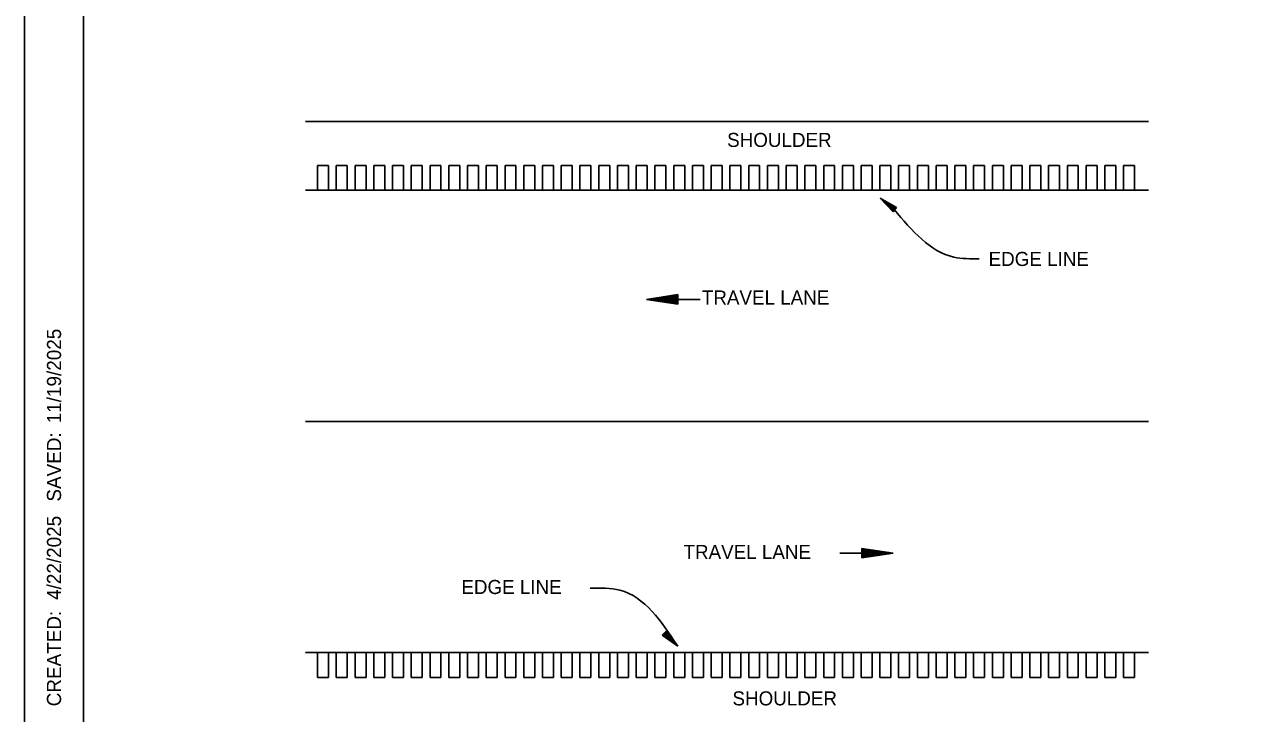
# Model space of a CAD drawing. Extents: x 1371343 to 1376243, y 378740 to 382184.
# Drawn here: x 1371343 to 1371864, y 380081 to 380374 of the extents above; entities that cross this region are included whole.
import ezdxf

# ---------------------------------------------------------------- set-up
doc = ezdxf.new("R2010")
doc.units = 0
for name, color, linetype in [('Default', 7, 'Continuous'), ('SHET_Border-Lines', 7, 'Continuous'), ('SHET_Border-Text', 7, 'Continuous')]:
    doc.layers.add(name, color=color, linetype=linetype)

msp = doc.modelspace()

# ---------------------------------------------------------------- linework, layer by layer
at = {"layer": 'Default'}
for p, q in [((1371462.15, 380332.32), (1371820.21, 380332.32)), ((1371467.32, 380303.13), (1371467.32, 380313.71)), ((1371467.32, 380313.71), (1371471.98, 380313.71)), ((1371471.98, 380303.13), (1371471.98, 380313.71)), ((1371475.28, 380303.13), (1371475.28, 380313.71)), ((1371475.28, 380313.71), (1371479.94, 380313.71)), ((1371479.94, 380303.13), (1371479.94, 380313.71)), ((1371483.24, 380303.13), (1371483.24, 380313.71)), ((1371483.24, 380313.71), (1371487.9, 380313.71)), ((1371487.9, 380303.13), (1371487.9, 380313.71)), ((1371491.2, 380303.13), (1371491.2, 380313.71)), ((1371491.2, 380313.71), (1371495.86, 380313.71)), ((1371495.86, 380303.13), (1371495.86, 380313.71)), ((1371499.16, 380303.13), (1371499.16, 380313.71)), ((1371499.16, 380313.71), (1371503.82, 380313.71)), ((1371503.82, 380303.13), (1371503.82, 380313.71)), ((1371507.12, 380303.13), (1371507.12, 380313.71)), ((1371507.12, 380313.71), (1371511.78, 380313.71)), ((1371511.78, 380303.13), (1371511.78, 380313.71)), ((1371515.08, 380303.13), (1371515.08, 380313.71)), ((1371515.08, 380313.71), (1371519.74, 380313.71)), ((1371519.74, 380303.13), (1371519.74, 380313.71)), ((1371523.04, 380303.13), (1371523.04, 380313.71)), ((1371523.04, 380313.71), (1371527.7, 380313.71)), ((1371527.7, 380303.13), (1371527.7, 380313.71)), ((1371531, 380303.13), (1371531, 380313.71)), ((1371531, 380313.71), (1371535.66, 380313.71)), ((1371535.66, 380303.13), (1371535.66, 380313.71)), ((1371538.96, 380303.13), (1371538.96, 380313.71)), ((1371538.96, 380313.71), (1371543.62, 380313.71)), ((1371543.62, 380303.13), (1371543.62, 380313.71)), ((1371546.92, 380303.13), (1371546.92, 380313.71)), ((1371546.92, 380313.71), (1371551.58, 380313.71)), ((1371551.58, 380303.13), (1371551.58, 380313.71)), ((1371554.88, 380303.13), (1371554.88, 380313.71)), ((1371554.88, 380313.71), (1371559.53, 380313.71)), ((1371559.53, 380303.13), (1371559.53, 380313.71)), ((1371562.84, 380303.13), (1371562.84, 380313.71)), ((1371562.84, 380313.71), (1371567.49, 380313.71)), ((1371567.49, 380303.13), (1371567.49, 380313.71)), ((1371570.8, 380303.13), (1371570.8, 380313.71)), ((1371570.8, 380313.71), (1371575.45, 380313.71)), ((1371575.45, 380303.13), (1371575.45, 380313.71)), ((1371578.76, 380303.13), (1371578.76, 380313.71)), ((1371578.76, 380313.71), (1371583.41, 380313.71)), ((1371583.41, 380303.13), (1371583.41, 380313.71)), ((1371586.72, 380303.13), (1371586.72, 380313.71)), ((1371586.72, 380303.13), (1371586.72, 380313.71)), ((1371586.72, 380313.71), (1371591.37, 380313.71)), ((1371591.37, 380303.13), (1371591.37, 380313.71)), ((1371594.68, 380303.13), (1371594.68, 380313.71)), ((1371594.68, 380313.71), (1371599.33, 380313.71)), ((1371599.33, 380303.13), (1371599.33, 380313.71)), ((1371602.64, 380303.13), (1371602.64, 380313.71)), ((1371602.64, 380313.71), (1371607.29, 380313.71)), ((1371607.29, 380303.13), (1371607.29, 380313.71)), ((1371610.6, 380303.13), (1371610.6, 380313.71)), ((1371610.6, 380313.71), (1371615.25, 380313.71)), ((1371615.25, 380303.13), (1371615.25, 380313.71)), ((1371618.55, 380303.13), (1371618.55, 380313.71)), ((1371618.55, 380313.71), (1371623.21, 380313.71)), ((1371623.21, 380303.13), (1371623.21, 380313.71)), ((1371626.51, 380303.13), (1371626.51, 380313.71)), ((1371626.51, 380313.71), (1371631.17, 380313.71)), ((1371631.17, 380303.13), (1371631.17, 380313.71)), ((1371634.47, 380303.13), (1371634.47, 380313.71)), ((1371634.47, 380313.71), (1371639.13, 380313.71)), ((1371639.13, 380303.13), (1371639.13, 380313.71)), ((1371642.43, 380303.13), (1371642.43, 380313.71)), ((1371642.43, 380313.71), (1371647.09, 380313.71)), ((1371647.09, 380303.13), (1371647.09, 380313.71)), ((1371650.39, 380303.13), (1371650.39, 380313.71)), ((1371650.39, 380313.71), (1371655.05, 380313.71)), ((1371655.05, 380303.13), (1371655.05, 380313.71)), ((1371658.35, 380303.13), (1371658.35, 380313.71)), ((1371658.35, 380313.71), (1371663.01, 380313.71)), ((1371663.01, 380303.13), (1371663.01, 380313.71)), ((1371666.31, 380303.13), (1371666.31, 380313.71)), ((1371666.31, 380313.71), (1371670.97, 380313.71)), ((1371670.97, 380303.13), (1371670.97, 380313.71)), ((1371674.27, 380303.13), (1371674.27, 380313.71)), ((1371674.27, 380313.71), (1371678.93, 380313.71)), ((1371678.93, 380303.13), (1371678.93, 380313.71)), ((1371682.23, 380303.13), (1371682.23, 380313.71)), ((1371682.23, 380313.71), (1371686.89, 380313.71)), ((1371686.89, 380303.13), (1371686.89, 380313.71)), ((1371690.19, 380303.13), (1371690.19, 380313.71)), ((1371690.19, 380313.71), (1371694.85, 380313.71)), ((1371694.85, 380303.13), (1371694.85, 380313.71)), ((1371698.15, 380303.13), (1371698.15, 380313.71)), ((1371698.15, 380313.71), (1371702.81, 380313.71)), ((1371702.81, 380303.13), (1371702.81, 380313.71)), ((1371706.11, 380303.13), (1371706.11, 380313.71)), ((1371706.11, 380313.71), (1371710.77, 380313.71)), ((1371710.77, 380303.13), (1371710.77, 380313.71)), ((1371714.07, 380303.13), (1371714.07, 380313.71)), ((1371714.07, 380313.71), (1371718.73, 380313.71)), ((1371718.73, 380303.13), (1371718.73, 380313.71)), ((1371722.03, 380303.13), (1371722.03, 380313.71)), ((1371722.03, 380313.71), (1371726.69, 380313.71)), ((1371726.69, 380303.13), (1371726.69, 380313.71)), ((1371729.99, 380303.13), (1371729.99, 380313.71)), ((1371729.99, 380313.71), (1371734.64, 380313.71)), ((1371734.64, 380303.13), (1371734.64, 380313.71)), ((1371737.95, 380303.13), (1371737.95, 380313.71)), ((1371737.95, 380313.71), (1371742.6, 380313.71)), ((1371742.6, 380303.13), (1371742.6, 380313.71)), ((1371745.91, 380303.13), (1371745.91, 380313.71)), ((1371745.91, 380313.71), (1371750.56, 380313.71)), ((1371750.56, 380303.13), (1371750.56, 380313.71)), ((1371753.87, 380303.13), (1371753.87, 380313.71)), ((1371753.87, 380313.71), (1371758.52, 380313.71)), ((1371758.52, 380303.13), (1371758.52, 380313.71)), ((1371761.83, 380303.13), (1371761.83, 380313.71)), ((1371761.83, 380313.71), (1371766.48, 380313.71)), ((1371766.48, 380303.13), (1371766.48, 380313.71)), ((1371769.79, 380303.13), (1371769.79, 380313.71)), ((1371769.79, 380313.71), (1371774.44, 380313.71)), ((1371774.44, 380303.13), (1371774.44, 380313.71)), ((1371777.75, 380303.13), (1371777.75, 380313.71)), ((1371777.75, 380313.71), (1371782.4, 380313.71)), ((1371782.4, 380303.13), (1371782.4, 380313.71)), ((1371785.7, 380303.13), (1371785.7, 380313.71)), ((1371785.7, 380313.71), (1371790.36, 380313.71)), ((1371790.36, 380303.13), (1371790.36, 380313.71)), ((1371793.66, 380303.13), (1371793.66, 380313.71)), ((1371793.66, 380313.71), (1371798.32, 380313.71)), ((1371798.32, 380303.13), (1371798.32, 380313.71)), ((1371801.62, 380303.13), (1371801.62, 380313.71)), ((1371801.62, 380313.71), (1371806.28, 380313.71)), ((1371806.28, 380303.13), (1371806.28, 380313.71)), ((1371809.58, 380303.13), (1371809.58, 380313.71)), ((1371809.58, 380313.71), (1371814.24, 380313.71)), ((1371814.24, 380303.13), (1371814.24, 380313.71)), ((1371462.15, 380303.13), (1371640.34, 380303.13)), ((1371471.98, 380303.13), (1371467.32, 380303.13)), ((1371479.94, 380303.13), (1371475.28, 380303.13)), ((1371487.9, 380303.13), (1371483.24, 380303.13)), ((1371495.86, 380303.13), (1371491.2, 380303.13)), ((1371503.82, 380303.13), (1371499.16, 380303.13)), ((1371511.78, 380303.13), (1371507.12, 380303.13)), ((1371519.74, 380303.13), (1371515.08, 380303.13)), ((1371527.7, 380303.13), (1371523.04, 380303.13)), ((1371535.66, 380303.13), (1371531, 380303.13)), ((1371543.62, 380303.13), (1371538.96, 380303.13)), ((1371551.58, 380303.13), (1371546.92, 380303.13)), ((1371559.53, 380303.13), (1371554.88, 380303.13)), ((1371567.49, 380303.13), (1371562.84, 380303.13)), ((1371575.45, 380303.13), (1371570.8, 380303.13)), ((1371583.41, 380303.13), (1371578.76, 380303.13)), ((1371591.37, 380303.13), (1371586.72, 380303.13)), ((1371599.33, 380303.13), (1371594.68, 380303.13)), ((1371607.29, 380303.13), (1371602.64, 380303.13)), ((1371615.25, 380303.13), (1371610.6, 380303.13)), ((1371623.21, 380303.13), (1371618.55, 380303.13)), ((1371631.17, 380303.13), (1371626.51, 380303.13)), ((1371639.13, 380303.13), (1371634.47, 380303.13)), ((1371820.21, 380303.13), (1371640.34, 380303.13)), ((1371647.09, 380303.13), (1371642.43, 380303.13)), ((1371655.05, 380303.13), (1371650.39, 380303.13)), ((1371663.01, 380303.13), (1371658.35, 380303.13)), ((1371670.97, 380303.13), (1371666.31, 380303.13)), ((1371678.93, 380303.13), (1371674.27, 380303.13)), ((1371686.89, 380303.13), (1371682.23, 380303.13)), ((1371694.85, 380303.13), (1371690.19, 380303.13)), ((1371702.81, 380303.13), (1371698.15, 380303.13)), ((1371710.77, 380303.13), (1371706.11, 380303.13)), ((1371711.7, 380293.95), (1371706.23, 380299.86)), ((1371713.19, 380295.82), (1371706.23, 380299.86)), ((1371718.73, 380303.13), (1371714.07, 380303.13)), ((1371726.69, 380303.13), (1371722.03, 380303.13)), ((1371734.64, 380303.13), (1371729.99, 380303.13)), ((1371742.6, 380303.13), (1371737.95, 380303.13)), ((1371750.56, 380303.13), (1371745.91, 380303.13)), ((1371758.52, 380303.13), (1371753.87, 380303.13)), ((1371766.48, 380303.13), (1371761.83, 380303.13)), ((1371774.44, 380303.13), (1371769.79, 380303.13)), ((1371782.4, 380303.13), (1371777.75, 380303.13)), ((1371790.36, 380303.13), (1371785.7, 380303.13)), ((1371798.32, 380303.13), (1371793.66, 380303.13)), ((1371806.28, 380303.13), (1371801.62, 380303.13)), ((1371814.24, 380303.13), (1371809.58, 380303.13)), ((1371711.82, 380294.11), (1371707.26, 380299.03)), ((1371713.07, 380295.66), (1371707.26, 380299.03)), ((1371712.93, 380295.5), (1371708.34, 380298.19)), ((1371711.96, 380294.27), (1371708.34, 380298.19)), ((1371712.08, 380294.43), (1371709.37, 380297.36)), ((1371712.82, 380295.35), (1371709.37, 380297.36)), ((1371712.68, 380295.19), (1371710.43, 380296.5)), ((1371712.2, 380294.59), (1371710.43, 380296.5)), ((1371712.56, 380295.03), (1371711.46, 380295.68)), ((1371712.32, 380294.75), (1371711.46, 380295.68)), ((1371711.7, 380293.95), (1371713.19, 380295.82)), ((1371620.37, 380258.83), (1371606.99, 380256.82)), ((1371620.37, 380258.49), (1371609.22, 380256.82)), ((1371620.37, 380258.17), (1371611.51, 380256.82)), ((1371620.37, 380258.83), (1371620.37, 380254.83)), ((1371629.76, 380256.82), (1371606.99, 380256.82)), ((1371620.37, 380254.83), (1371606.99, 380256.82)), ((1371620.37, 380255.15), (1371609.22, 380256.82)), ((1371620.37, 380255.51), (1371611.51, 380256.82)), ((1371620.37, 380257.81), (1371613.72, 380256.82)), ((1371620.37, 380255.82), (1371613.72, 380256.82)), ((1371620.37, 380257.46), (1371616.01, 380256.82)), ((1371620.37, 380256.16), (1371616.01, 380256.82)), ((1371620.37, 380257.16), (1371618.24, 380256.82)), ((1371620.37, 380256.5), (1371618.24, 380256.82)), ((1371462.15, 380204.96), (1371820.21, 380204.96)), ((1371689.04, 380149.07), (1371711.8, 380149.07)), ((1371698.43, 380151.04), (1371711.8, 380149.07)), ((1371698.43, 380147.06), (1371698.43, 380151.04)), ((1371698.43, 380150.72), (1371709.57, 380149.07)), ((1371698.43, 380150.38), (1371707.28, 380149.07)), ((1371698.43, 380150.04), (1371705.07, 380149.07)), ((1371698.43, 380149.71), (1371702.79, 380149.07)), ((1371698.43, 380149.39), (1371700.56, 380149.07)), ((1371698.43, 380147.06), (1371711.8, 380149.07)), ((1371698.43, 380148.41), (1371702.79, 380149.07)), ((1371698.43, 380147.72), (1371707.28, 380149.07)), ((1371698.43, 380147.38), (1371709.57, 380149.07)), ((1371698.43, 380148.05), (1371705.07, 380149.07)), ((1371698.43, 380148.73), (1371700.56, 380149.07)), ((1371615.37, 380115.92), (1371613.72, 380114.21)), ((1371613.72, 380114.21), (1371620.27, 380109.51)), ((1371613.86, 380114.35), (1371619.31, 380110.45)), ((1371614, 380114.49), (1371618.32, 380111.4)), ((1371614.14, 380114.62), (1371617.38, 380112.32)), ((1371614.28, 380114.76), (1371616.41, 380113.25)), ((1371614.42, 380114.92), (1371615.45, 380114.19)), ((1371614.67, 380115.18), (1371615.45, 380114.19)), ((1371614.81, 380115.32), (1371616.41, 380113.25)), ((1371614.95, 380115.48), (1371617.38, 380112.32)), ((1371615.09, 380115.62), (1371618.32, 380111.4)), ((1371615.23, 380115.76), (1371619.31, 380110.45)), ((1371615.37, 380115.92), (1371620.27, 380109.51)), ((1371462.15, 380106.8), (1371640.34, 380106.8)), ((1371471.98, 380106.8), (1371467.32, 380106.8)), ((1371467.32, 380106.8), (1371467.32, 380096.22)), ((1371471.98, 380106.8), (1371471.98, 380096.22)), ((1371479.94, 380106.8), (1371475.28, 380106.8)), ((1371475.28, 380106.8), (1371475.28, 380096.22)), ((1371479.94, 380106.8), (1371479.94, 380096.22)), ((1371487.9, 380106.8), (1371483.24, 380106.8)), ((1371483.24, 380106.8), (1371483.24, 380096.22)), ((1371487.9, 380106.8), (1371487.9, 380096.22)), ((1371495.86, 380106.8), (1371491.2, 380106.8)), ((1371491.2, 380106.8), (1371491.2, 380096.22)), ((1371495.86, 380106.8), (1371495.86, 380096.22)), ((1371503.82, 380106.8), (1371499.16, 380106.8)), ((1371499.16, 380106.8), (1371499.16, 380096.22)), ((1371503.82, 380106.8), (1371503.82, 380096.22)), ((1371511.78, 380106.8), (1371507.12, 380106.8)), ((1371507.12, 380106.8), (1371507.12, 380096.22)), ((1371511.78, 380106.8), (1371511.78, 380096.22)), ((1371519.74, 380106.8), (1371515.08, 380106.8)), ((1371515.08, 380106.8), (1371515.08, 380096.22)), ((1371519.74, 380106.8), (1371519.74, 380096.22)), ((1371527.7, 380106.8), (1371523.04, 380106.8)), ((1371523.04, 380106.8), (1371523.04, 380096.22)), ((1371527.7, 380106.8), (1371527.7, 380096.22)), ((1371535.66, 380106.8), (1371531, 380106.8)), ((1371531, 380106.8), (1371531, 380096.22)), ((1371535.66, 380106.8), (1371535.66, 380096.22)), ((1371543.62, 380106.8), (1371538.96, 380106.8)), ((1371538.96, 380106.8), (1371538.96, 380096.22)), ((1371543.62, 380106.8), (1371543.62, 380096.22)), ((1371551.58, 380106.8), (1371546.92, 380106.8)), ((1371546.92, 380106.8), (1371546.92, 380096.22)), ((1371551.58, 380106.8), (1371551.58, 380096.22)), ((1371559.53, 380106.8), (1371554.88, 380106.8)), ((1371554.88, 380106.8), (1371554.88, 380096.22)), ((1371559.53, 380106.8), (1371559.53, 380096.22)), ((1371567.49, 380106.8), (1371562.84, 380106.8)), ((1371562.84, 380106.8), (1371562.84, 380096.22)), ((1371567.49, 380106.8), (1371567.49, 380096.22)), ((1371575.45, 380106.8), (1371570.8, 380106.8)), ((1371570.8, 380106.8), (1371570.8, 380096.22)), ((1371575.45, 380106.8), (1371575.45, 380096.22)), ((1371583.41, 380106.8), (1371578.76, 380106.8)), ((1371578.76, 380106.8), (1371578.76, 380096.22)), ((1371583.41, 380106.8), (1371583.41, 380096.22)), ((1371591.37, 380106.8), (1371586.72, 380106.8)), ((1371586.72, 380106.8), (1371586.72, 380096.22)), ((1371591.37, 380106.8), (1371591.37, 380096.22)), ((1371599.33, 380106.8), (1371594.68, 380106.8)), ((1371594.68, 380106.8), (1371594.68, 380096.22)), ((1371599.33, 380106.8), (1371599.33, 380096.22)), ((1371607.29, 380106.8), (1371602.64, 380106.8)), ((1371602.64, 380106.8), (1371602.64, 380096.22)), ((1371607.29, 380106.8), (1371607.29, 380096.22)), ((1371615.25, 380106.8), (1371610.6, 380106.8)), ((1371610.6, 380106.8), (1371610.6, 380096.22)), ((1371615.25, 380106.8), (1371615.25, 380096.22)), ((1371623.21, 380106.8), (1371618.55, 380106.8)), ((1371618.55, 380106.8), (1371618.55, 380096.22)), ((1371623.21, 380106.8), (1371623.21, 380096.22)), ((1371631.17, 380106.8), (1371626.51, 380106.8)), ((1371626.51, 380106.8), (1371626.51, 380096.22)), ((1371631.17, 380106.8), (1371631.17, 380096.22)), ((1371639.13, 380106.8), (1371634.47, 380106.8)), ((1371634.47, 380106.8), (1371634.47, 380096.22)), ((1371639.13, 380106.8), (1371639.13, 380096.22)), ((1371820.21, 380106.8), (1371640.34, 380106.8)), ((1371647.09, 380106.8), (1371642.43, 380106.8)), ((1371642.43, 380106.8), (1371642.43, 380096.22)), ((1371647.09, 380106.8), (1371647.09, 380096.22)), ((1371655.05, 380106.8), (1371650.39, 380106.8)), ((1371650.39, 380106.8), (1371650.39, 380096.22)), ((1371655.05, 380106.8), (1371655.05, 380096.22)), ((1371663.01, 380106.8), (1371658.35, 380106.8)), ((1371658.35, 380106.8), (1371658.35, 380096.22)), ((1371663.01, 380106.8), (1371663.01, 380096.22)), ((1371670.97, 380106.8), (1371666.31, 380106.8)), ((1371666.31, 380106.8), (1371666.31, 380096.22)), ((1371670.97, 380106.8), (1371670.97, 380096.22)), ((1371678.93, 380106.8), (1371674.27, 380106.8)), ((1371674.27, 380106.8), (1371674.27, 380096.22)), ((1371678.93, 380106.8), (1371678.93, 380096.22)), ((1371686.89, 380106.8), (1371682.23, 380106.8)), ((1371682.23, 380106.8), (1371682.23, 380096.22)), ((1371686.89, 380106.8), (1371686.89, 380096.22)), ((1371694.85, 380106.8), (1371690.19, 380106.8)), ((1371690.19, 380106.8), (1371690.19, 380096.22)), ((1371694.85, 380106.8), (1371694.85, 380096.22)), ((1371702.81, 380106.8), (1371698.15, 380106.8)), ((1371698.15, 380106.8), (1371698.15, 380096.22)), ((1371702.81, 380106.8), (1371702.81, 380096.22)), ((1371710.77, 380106.8), (1371706.11, 380106.8)), ((1371706.11, 380106.8), (1371706.11, 380096.22)), ((1371710.77, 380106.8), (1371710.77, 380096.22)), ((1371718.73, 380106.8), (1371714.07, 380106.8)), ((1371714.07, 380106.8), (1371714.07, 380096.22)), ((1371718.73, 380106.8), (1371718.73, 380096.22)), ((1371726.69, 380106.8), (1371722.03, 380106.8)), ((1371722.03, 380106.8), (1371722.03, 380096.22)), ((1371726.69, 380106.8), (1371726.69, 380096.22)), ((1371734.64, 380106.8), (1371729.99, 380106.8)), ((1371729.99, 380106.8), (1371729.99, 380096.22)), ((1371734.64, 380106.8), (1371734.64, 380096.22)), ((1371742.6, 380106.8), (1371737.95, 380106.8)), ((1371737.95, 380106.8), (1371737.95, 380096.22)), ((1371742.6, 380106.8), (1371742.6, 380096.22)), ((1371750.56, 380106.8), (1371745.91, 380106.8)), ((1371745.91, 380106.8), (1371745.91, 380096.22)), ((1371750.56, 380106.8), (1371750.56, 380096.22)), ((1371758.52, 380106.8), (1371753.87, 380106.8)), ((1371753.87, 380106.8), (1371753.87, 380096.22)), ((1371758.52, 380106.8), (1371758.52, 380096.22)), ((1371766.48, 380106.8), (1371761.83, 380106.8)), ((1371761.83, 380106.8), (1371761.83, 380096.22)), ((1371766.48, 380106.8), (1371766.48, 380096.22)), ((1371774.44, 380106.8), (1371769.79, 380106.8)), ((1371769.79, 380106.8), (1371769.79, 380096.22)), ((1371774.44, 380106.8), (1371774.44, 380096.22)), ((1371782.4, 380106.8), (1371777.75, 380106.8)), ((1371777.75, 380106.8), (1371777.75, 380096.22)), ((1371782.4, 380106.8), (1371782.4, 380096.22)), ((1371790.36, 380106.8), (1371785.7, 380106.8)), ((1371785.7, 380106.8), (1371785.7, 380096.22)), ((1371790.36, 380106.8), (1371790.36, 380096.22)), ((1371798.32, 380106.8), (1371793.66, 380106.8)), ((1371793.66, 380106.8), (1371793.66, 380096.22)), ((1371798.32, 380106.8), (1371798.32, 380096.22)), ((1371806.28, 380106.8), (1371801.62, 380106.8)), ((1371801.62, 380106.8), (1371801.62, 380096.22)), ((1371806.28, 380106.8), (1371806.28, 380096.22)), ((1371814.24, 380106.8), (1371809.58, 380106.8)), ((1371809.58, 380106.8), (1371809.58, 380096.22)), ((1371814.24, 380106.8), (1371814.24, 380096.22)), ((1371467.32, 380096.22), (1371471.98, 380096.22)), ((1371475.28, 380096.22), (1371479.94, 380096.22)), ((1371483.24, 380096.22), (1371487.9, 380096.22)), ((1371491.2, 380096.22), (1371495.86, 380096.22)), ((1371499.16, 380096.22), (1371503.82, 380096.22)), ((1371507.12, 380096.22), (1371511.78, 380096.22)), ((1371515.08, 380096.22), (1371519.74, 380096.22)), ((1371523.04, 380096.22), (1371527.7, 380096.22)), ((1371531, 380096.22), (1371535.66, 380096.22)), ((1371538.96, 380096.22), (1371543.62, 380096.22)), ((1371546.92, 380096.22), (1371551.58, 380096.22)), ((1371554.88, 380096.22), (1371559.53, 380096.22)), ((1371562.84, 380096.22), (1371567.49, 380096.22)), ((1371570.8, 380096.22), (1371575.45, 380096.22)), ((1371578.76, 380096.22), (1371583.41, 380096.22)), ((1371586.72, 380096.22), (1371591.37, 380096.22)), ((1371594.68, 380096.22), (1371599.33, 380096.22)), ((1371602.64, 380096.22), (1371607.29, 380096.22)), ((1371610.6, 380096.22), (1371615.25, 380096.22)), ((1371618.55, 380096.22), (1371623.21, 380096.22)), ((1371626.51, 380096.22), (1371631.17, 380096.22)), ((1371634.47, 380096.22), (1371639.13, 380096.22)), ((1371642.43, 380096.22), (1371647.09, 380096.22)), ((1371650.39, 380096.22), (1371655.05, 380096.22)), ((1371658.35, 380096.22), (1371663.01, 380096.22)), ((1371666.31, 380096.22), (1371670.97, 380096.22)), ((1371674.27, 380096.22), (1371678.93, 380096.22)), ((1371682.23, 380096.22), (1371686.89, 380096.22)), ((1371690.19, 380096.22), (1371694.85, 380096.22)), ((1371698.15, 380096.22), (1371702.81, 380096.22)), ((1371706.11, 380096.22), (1371710.77, 380096.22)), ((1371714.07, 380096.22), (1371718.73, 380096.22)), ((1371722.03, 380096.22), (1371726.69, 380096.22)), ((1371729.99, 380096.22), (1371734.64, 380096.22)), ((1371737.95, 380096.22), (1371742.6, 380096.22)), ((1371745.91, 380096.22), (1371750.56, 380096.22)), ((1371753.87, 380096.22), (1371758.52, 380096.22)), ((1371761.83, 380096.22), (1371766.48, 380096.22)), ((1371769.79, 380096.22), (1371774.44, 380096.22)), ((1371777.75, 380096.22), (1371782.4, 380096.22)), ((1371785.7, 380096.22), (1371790.36, 380096.22)), ((1371793.66, 380096.22), (1371798.32, 380096.22)), ((1371801.62, 380096.22), (1371806.28, 380096.22)), ((1371809.58, 380096.22), (1371814.24, 380096.22))]:
    msp.add_line(p, q, dxfattribs=at)
msp.add_lwpolyline([(1371342.92, 380940.49), (1371342.92, 379840.49), (1373042.92, 379840.49), (1373042.92, 380940.49)], close=True, dxfattribs=at)
for points in [[(1371748.3, 380273.99), (1371737.51, 380274.77), (1371712.16, 380294.97)], [(1371583.06, 380134.15), (1371595.73, 380133.27), (1371620.27, 380109.51)]]:
    msp.add_spline(points, degree=3, dxfattribs=at)
at = {"layer": 'SHET_Border-Lines'}
for points in [[(1371342.92, 379840.49), (1373042.92, 379840.49), (1373042.92, 380940.49), (1371342.92, 380940.49)], [(1371367.92, 379865.49), (1373017.92, 379865.49), (1373017.92, 380915.49), (1371367.92, 380915.49)]]:
    msp.add_lwpolyline(points, close=True, dxfattribs=at)

# ---------------------------------------------------------------- texts
at = {"layer": 'Default'}
for s, height, p in [('SHOULDER', 5.97, (1371641.24, 380321.55)), ('EDGE LINE', 5.97, (1371752.26, 380270.99)), ('TRAVEL LANE', 5.9696, (1371630.51, 380254.62)), ('TRAVEL LANE', 5.9696, (1371622.72, 380146.55)), ('EDGE LINE', 5.97, (1371528.39, 380131.67)), ('SHOULDER', 5.97, (1371643.51, 380084.36))]:
    msp.add_text(s, height=height, dxfattribs=at).set_placement(p)
at = {"layer": 'SHET_Border-Text'}
for s, p in [('11/19/2025', (1371358.42, 380204.19)), ('  SAVED: ', (1371358.42, 380166.46)), ('4/22/2025', (1371358.42, 380129.18)), ('     CREATED: ', (1371358.42, 380072.82))]:
    msp.add_text(s, height=6, rotation=90, dxfattribs=at).set_placement(p)

doc.saveas('drawing.dxf')
